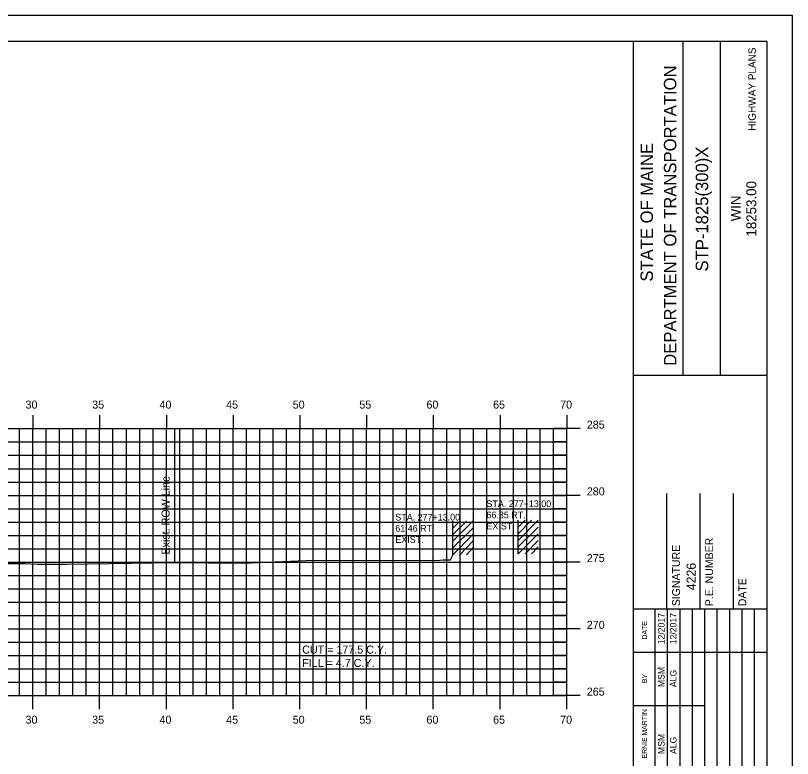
# Model space of a CAD drawing. Extents: x 854008 to 854178, y 366268 to 366378.
# Drawn here: x 854119.8 to 854178, y 366322.5 to 366378.2 of the extents above; entities that cross this region are included whole.
import ezdxf

# ---------------------------------------------------------------- set-up
doc = ezdxf.new("R2010")
doc.units = 0
for name, color, linetype in [('ANNOTATION', 7, 'Continuous'), ('BORDER', 7, 'Continuous'), ('D_Text_Monospaced', 7, 'Continuous'), ('E_ROW_Line', 7, 'Continuous'), ('H_V ANNOTATION', 7, 'Continuous'), ('HIGHWAY_TITLE', 7, 'Continuous'), ('MAJOR', 7, 'Continuous'), ('MINOR', 7, 'Continuous'), ('PLOT BOUNDARY', 7, 'Continuous'), ('S_Buildings', 7, 'Continuous'), ('S_Roadway_Centerline', 7, 'Continuous')]:
    doc.layers.add(name, color=color, linetype=linetype)

msp = doc.modelspace()

# ---------------------------------------------------------------- linework, layer by layer
at = {"layer": 'BORDER'}
for p, q in [((854176.103, 366376.236), (854016.103, 366376.236)), ((854166.103, 366271.236), (854166.103, 366376.239)), ((854169.832, 366351.234), (854169.832, 366376.234)), ((854172.627, 366351.234), (854172.627, 366376.234)), ((854176.103, 366271.236), (854176.103, 366376.236)), ((854166.104, 366351.231), (854176.103, 366351.231)), ((854168.603, 366333.739), (854168.603, 366342.387)), ((854171.103, 366333.739), (854171.103, 366342.387)), ((854173.603, 366333.739), (854173.603, 366342.387)), ((854166.103, 366333.739), (854176.103, 366333.739))]:
    msp.add_line(p, q, dxfattribs=at)
for points in [[(854167.718, 366330.489), (854167.718, 366333.739)], [(854168.651, 366316.242), (854168.651, 366333.739)], [(854169.582, 366333.739), (854169.582, 366316.242)], [(854170.514, 366316.242), (854170.514, 366333.739)], [(854171.446, 366316.242), (854171.446, 366333.739)], [(854172.377, 366316.242), (854172.377, 366333.739)], [(854173.309, 366316.242), (854173.309, 366333.739)], [(854174.241, 366316.242), (854174.241, 366333.739)], [(854175.172, 366316.242), (854175.172, 366333.739)], [(854167.719, 366316.242), (854167.719, 366333.033)], [(854166.103, 366330.489), (854176.103, 366330.489)], [(854166.103, 366326.489), (854167.719, 366326.489)], [(854167.718, 366326.489), (854171.445, 366326.489)]]:
    msp.add_lwpolyline(points, dxfattribs=at)
at = {"layer": 'E_ROW_Line'}
msp.add_line((854131.745, 366337.203), (854131.745, 366347.203), dxfattribs=at)
at = {"layer": 'MAJOR'}
for p, q in [((854121.103, 366348.238), (854121.103, 366347.236)), ((854126.103, 366348.238), (854126.103, 366347.236)), ((854131.103, 366348.238), (854131.103, 366347.236)), ((854136.103, 366348.238), (854136.103, 366347.236)), ((854141.103, 366348.238), (854141.103, 366347.236)), ((854146.103, 366348.238), (854146.103, 366347.236)), ((854151.103, 366348.238), (854151.103, 366347.236)), ((854156.103, 366348.238), (854156.103, 366347.236)), ((854161.103, 366348.238), (854161.103, 366347.236)), ((854021.103, 366347.236), (854161.103, 366347.236)), ((854021.103, 366347.236), (854161.103, 366347.236)), ((854121.103, 366327.236), (854121.103, 366347.236)), ((854126.103, 366327.236), (854126.103, 366347.236)), ((854131.103, 366327.236), (854131.103, 366347.236)), ((854136.103, 366327.236), (854136.103, 366347.236)), ((854141.103, 366327.236), (854141.103, 366347.236)), ((854146.103, 366327.236), (854146.103, 366347.236)), ((854151.103, 366327.236), (854151.103, 366347.236)), ((854156.103, 366327.236), (854156.103, 366347.236)), ((854162.105, 366347.236), (854160.101, 366347.236)), ((854161.103, 366327.236), (854161.103, 366347.236)), ((854161.103, 366327.236), (854161.103, 366347.236)), ((854021.103, 366342.236), (854161.103, 366342.236)), ((854162.105, 366342.236), (854160.101, 366342.236)), ((854021.103, 366337.236), (854161.103, 366337.236)), ((854162.105, 366337.236), (854160.101, 366337.236)), ((854021.103, 366332.236), (854161.103, 366332.236)), ((854162.105, 366332.236), (854160.101, 366332.236)), ((854021.103, 366327.236), (854161.103, 366327.236)), ((854021.103, 366327.236), (854161.103, 366327.236)), ((854121.103, 366326.234), (854121.103, 366327.236)), ((854126.103, 366326.234), (854126.103, 366327.236)), ((854131.103, 366326.234), (854131.103, 366327.236)), ((854136.103, 366326.234), (854136.103, 366327.236)), ((854141.103, 366326.234), (854141.103, 366327.236)), ((854146.103, 366326.234), (854146.103, 366327.236)), ((854151.103, 366326.234), (854151.103, 366327.236)), ((854156.103, 366326.234), (854156.103, 366327.236)), ((854162.105, 366327.236), (854160.101, 366327.236)), ((854161.103, 366326.234), (854161.103, 366327.236))]:
    msp.add_line(p, q, dxfattribs=at)
at = {"layer": 'MINOR'}
for p, q in [((854120.103, 366327.236), (854120.103, 366347.236)), ((854122.103, 366327.236), (854122.103, 366347.236)), ((854123.103, 366327.236), (854123.103, 366347.236)), ((854124.103, 366327.236), (854124.103, 366347.236)), ((854125.103, 366327.236), (854125.103, 366347.236)), ((854127.103, 366327.236), (854127.103, 366347.236)), ((854128.103, 366327.236), (854128.103, 366347.236)), ((854129.103, 366327.236), (854129.103, 366347.236)), ((854130.103, 366327.236), (854130.103, 366347.236)), ((854132.103, 366327.236), (854132.103, 366347.236)), ((854133.103, 366327.236), (854133.103, 366347.236)), ((854134.103, 366327.236), (854134.103, 366347.236)), ((854135.103, 366327.236), (854135.103, 366347.236)), ((854137.103, 366327.236), (854137.103, 366347.236)), ((854138.103, 366327.236), (854138.103, 366347.236)), ((854139.103, 366327.236), (854139.103, 366347.236)), ((854140.103, 366327.236), (854140.103, 366347.236)), ((854142.103, 366327.236), (854142.103, 366347.236)), ((854143.103, 366327.236), (854143.103, 366347.236)), ((854144.103, 366327.236), (854144.103, 366347.236)), ((854145.103, 366327.236), (854145.103, 366347.236)), ((854147.103, 366327.236), (854147.103, 366347.236)), ((854148.103, 366327.236), (854148.103, 366347.236)), ((854149.103, 366327.236), (854149.103, 366347.236)), ((854150.103, 366327.236), (854150.103, 366347.236)), ((854152.103, 366327.236), (854152.103, 366347.236)), ((854153.103, 366327.236), (854153.103, 366347.236)), ((854154.103, 366327.236), (854154.103, 366347.236)), ((854155.103, 366327.236), (854155.103, 366347.236)), ((854157.103, 366327.236), (854157.103, 366347.236)), ((854158.103, 366327.236), (854158.103, 366347.236)), ((854159.103, 366327.236), (854159.103, 366347.236)), ((854160.103, 366327.236), (854160.103, 366347.236)), ((854021.103, 366346.236), (854161.103, 366346.236)), ((854161.103, 366346.236), (854160.101, 366346.236)), ((854021.103, 366345.236), (854161.103, 366345.236)), ((854161.103, 366345.236), (854160.101, 366345.236)), ((854021.103, 366344.236), (854161.103, 366344.236)), ((854161.103, 366344.236), (854160.101, 366344.236)), ((854021.103, 366343.236), (854161.103, 366343.236)), ((854161.103, 366343.236), (854160.101, 366343.236)), ((854021.103, 366341.236), (854161.103, 366341.236)), ((854161.103, 366341.236), (854160.101, 366341.236)), ((854021.103, 366340.236), (854161.103, 366340.236)), ((854161.103, 366340.236), (854160.101, 366340.236)), ((854021.103, 366339.236), (854161.103, 366339.236)), ((854161.103, 366339.236), (854160.101, 366339.236)), ((854021.103, 366338.236), (854161.103, 366338.236)), ((854161.103, 366338.236), (854160.101, 366338.236)), ((854021.103, 366336.236), (854161.103, 366336.236)), ((854161.103, 366336.236), (854160.101, 366336.236)), ((854021.103, 366335.236), (854161.103, 366335.236)), ((854161.103, 366335.236), (854160.101, 366335.236)), ((854021.103, 366334.236), (854161.103, 366334.236)), ((854161.103, 366334.236), (854160.101, 366334.236)), ((854021.103, 366333.236), (854161.103, 366333.236)), ((854161.103, 366333.236), (854160.101, 366333.236)), ((854021.103, 366331.236), (854161.103, 366331.236)), ((854161.103, 366331.236), (854160.101, 366331.236)), ((854021.103, 366330.236), (854161.103, 366330.236)), ((854161.103, 366330.236), (854160.101, 366330.236)), ((854021.103, 366329.236), (854161.103, 366329.236)), ((854161.103, 366329.236), (854160.101, 366329.236)), ((854021.103, 366328.236), (854161.103, 366328.236)), ((854161.103, 366328.236), (854160.101, 366328.236))]:
    msp.add_line(p, q, dxfattribs=at)
at = {"layer": 'PLOT BOUNDARY'}
msp.add_lwpolyline([(854008.01, 366268.177), (854178.01, 366268.177), (854178.01, 366378.177), (854008.01, 366378.177)], close=True, dxfattribs=at)
at = {"layer": 'S_Buildings'}
for p, q in [((854152.559, 366337.79), (854152.559, 366340.316)), ((854152.559, 366338.807), (854154.069, 366340.316)), ((854152.559, 366339.299), (854153.576, 366340.316)), ((854152.559, 366339.791), (854153.084, 366340.316)), ((854157.452, 366337.851), (854157.452, 366340.377)), ((854157.452, 366338.868), (854158.961, 366340.377)), ((854157.452, 366339.36), (854158.469, 366340.377)), ((854157.452, 366339.852), (854157.977, 366340.377)), ((854152.559, 366338.315), (854154.069, 366339.791)), ((854157.452, 366338.376), (854158.961, 366339.852)), ((854152.559, 366337.79), (854154.069, 366339.299)), ((854157.452, 366337.851), (854158.961, 366339.36)), ((854153.084, 366337.79), (854154.069, 366338.807)), ((854157.977, 366337.851), (854158.961, 366338.868)), ((854153.576, 366337.79), (854154.069, 366338.315)), ((854158.469, 366337.851), (854158.961, 366338.376))]:
    msp.add_line(p, q, dxfattribs=at)
at = {"layer": 'S_Roadway_Centerline'}
msp.add_lwpolyline([(854119.066, 366337.139), (854120.534, 366337.135), (854121.45, 366337.093), (854123.584, 366337.081), (854131.654, 366337.203), (854136.855, 366337.168), (854141.585, 366337.354), (854151.587, 366337.393), (854151.841, 366337.399), (854152.401, 366337.406), (854152.555, 366337.768), (854152.559, 366337.79)], dxfattribs=at)

# ---------------------------------------------------------------- texts
at = {"layer": 'ANNOTATION'}
msp.add_text('4226', height=0.69, rotation=90, dxfattribs=at).set_placement((854170.768, 366335.13))
for s, p in [('CUT = 177.5 C.Y.', (854141.279, 366330.386)), ('FILL = 4.7 C.Y.', (854141.279, 366329.384))]:
    msp.add_text(s, height=0.6, dxfattribs=at).set_placement(p)
at = {"layer": 'BORDER'}
for s, height, p in [('DEPARTMENT OF TRANSPORTATION', 0.93176, (854169.31, 366351.942)), ('STATE OF MAINE', 0.93176, (854167.559, 366358.248)), ('STP-1825(300)X', 0.93176, (854171.695, 366359.008)), ('18253.00', 0.7453, (854175.299, 366361.623)), ('WIN', 0.7453, (854174.14, 366362.766)), ('P.E. NUMBER', 0.59055, (854172.064, 366333.932)), ('SIGNATURE', 0.5906, (854169.584, 366333.932)), ('DATE', 0.5906, (854174.544, 366333.932)), ('12/2017', 0.4845, (854168.426, 366331.081)), ('12/2017', 0.4845, (854169.321, 366331.081)), ('DATE', 0.3714, (854167.108, 366331.445)), ('MSM', 0.4845, (854168.426, 366327.872)), ('ALG', 0.4845, (854169.321, 366327.872)), ('BY', 0.3714, (854167.108, 366328.174)), ('ERNIE MARTIN', 0.37275, (854167.108, 366322.531)), ('MSM', 0.4845, (854168.426, 366322.863)), ('ALG', 0.4845, (854169.321, 366322.863))]:
    msp.add_text(s, height=height, rotation=90, dxfattribs=at).set_placement(p)
at = {"layer": 'D_Text_Monospaced'}
for s, height, p in [('STA. 277+13.00', 0.49998, (854155.084, 366341.357)), ('STA. 277+13.00', 0.49998, (854148.256, 366340.352)), ('66.35 RT.', 0.5, (854155.084, 366340.523)), ('EXIST. ', 0.5, (854155.084, 366339.683)), ('61.46 RT.', 0.5, (854148.256, 366339.518)), ('EXIST. ', 0.5, (854148.256, 366338.678))]:
    msp.add_text(s, height=height, dxfattribs=at).set_placement(p)
at = {"layer": 'E_ROW_Line'}
msp.add_text('Exist. ROW Line', height=0.6, rotation=90, dxfattribs=at).set_placement((854131.345, 366337.803))
at = {"layer": 'H_V ANNOTATION'}
for s, p in [('30', (854120.552, 366348.736)), ('35', (854125.544, 366348.736)), ('40', (854130.589, 366348.736)), ('45', (854135.581, 366348.736)), ('50', (854140.568, 366348.736)), ('55', (854145.56, 366348.736)), ('60', (854150.589, 366348.736)), ('65', (854155.581, 366348.736)), ('70', (854160.605, 366348.736)), ('285', (854162.603, 366347.236)), ('280', (854162.603, 366342.236)), ('275', (854162.603, 366337.236)), ('270', (854162.603, 366332.236)), ('265', (854162.603, 366327.236)), ('30', (854120.552, 366325.136)), ('35', (854125.544, 366325.136)), ('40', (854130.589, 366325.136)), ('45', (854135.581, 366325.136)), ('50', (854140.568, 366325.136)), ('55', (854145.56, 366325.136)), ('60', (854150.589, 366325.136)), ('65', (854155.581, 366325.136)), ('70', (854160.605, 366325.136))]:
    msp.add_text(s, height=0.6, dxfattribs=at).set_placement(p)
at = {"layer": 'HIGHWAY_TITLE'}
msp.add_text('HIGHWAY PLANS', height=0.55901, rotation=90, dxfattribs=at).set_placement((854175.262, 366369.552))

doc.saveas('drawing.dxf')
